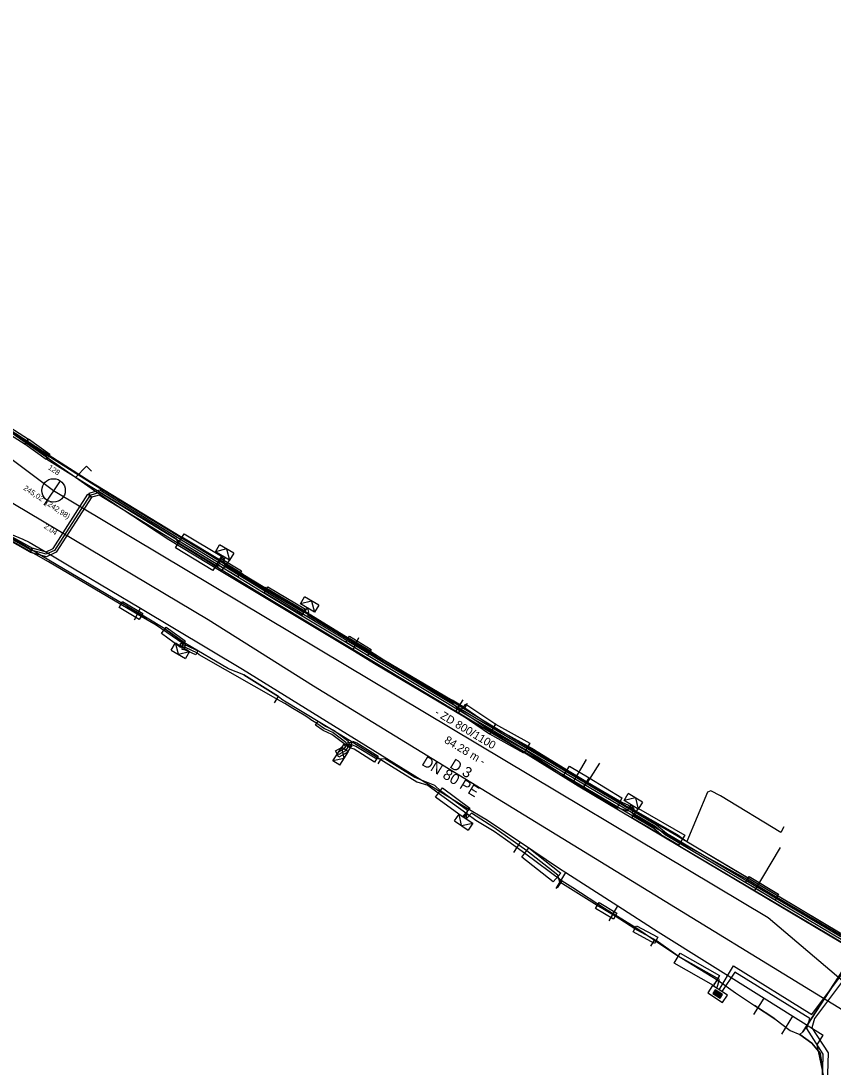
# Model space of a CAD drawing. Extents: x -600636 to -600148, y -1203980 to -1203569.
# Drawn here: x -600313.9 to -600244.6, y -1203728.9 to -1203639.7 of the extents above; entities that cross this region are included whole.
import ezdxf

# ---------------------------------------------------------------- set-up
doc = ezdxf.new("R2010")
doc.units = 0
for name, color, linetype in [('Cetin zam průběh', 7, 'Continuous'), ('EON objekty', 7, 'Continuous'), ('EON podzemní NN', 7, 'Continuous'), ('EON podzemní VN', 7, 'Continuous'), ('GasNet NTL', 7, 'Continuous'), ('Implicitní', 7, 'Continuous'), ('VaK Břeclav_kanalizace', 7, 'Continuous'), ('VaK Břeclav_kanalizace_popis', 7, 'Continuous'), ('Vak Břeclav_vodovod', 7, 'Continuous'), ('Vak Břeclav_vodovod_popis', 7, 'Continuous'), ('Vrstva 9', 7, 'Continuous')]:
    doc.layers.add(name, color=color, linetype=linetype)

# ---------------------------------------------------------------- blocks, each defined once
blk = doc.blocks.new('NN630')
at = {"layer": 'Vrstva 9'}
for points in [[(-0.003, -0.7), (-0.703, 0)], [(-0.703, -0.7), (-0.703, 0), (0.697, 0), (0.697, -0.7)], [(-0.703, -0.7), (0.697, -0.7)], [(-0.003, -0.7), (0.697, 0)]]:
    blk.add_lwpolyline(points, dxfattribs=at)
blk = doc.blocks.new('NN620')
at = {"layer": 'EON objekty'}
for points in [[(0.752, 0.004), (-0.748, 0.004)], [(-0.748, 0.004), (-0.748, -0.746)], [(0.752, -0.746), (0.752, 0.004)], [(-0.748, -0.746), (0.752, -0.746)], [(0.368, -0.18), (-0.376, -0.18)], [(-0.376, -0.18), (-0.376, -0.558)], [(-0.376, -0.558), (0.368, -0.558)], [(0.321, -0.227), (-0.329, -0.227)], [(-0.329, -0.227), (-0.329, -0.51)], [(-0.329, -0.51), (0.321, -0.51)], [(0.274, -0.274), (-0.281, -0.274)], [(-0.281, -0.274), (-0.281, -0.463)], [(-0.281, -0.463), (0.274, -0.463)], [(0.227, -0.321), (-0.234, -0.321)], [(-0.234, -0.321), (-0.234, -0.416)], [(-0.234, -0.416), (0.227, -0.416)], [(-0.193, -0.369), (0.185, -0.369)], [(0.227, -0.416), (0.227, -0.321)], [(0.274, -0.463), (0.274, -0.274)], [(0.321, -0.51), (0.321, -0.227)], [(0.368, -0.558), (0.368, -0.18)]]:
    blk.add_lwpolyline(points, dxfattribs=at)
blk = doc.blocks.new('MoSymbol 2')
at = {"layer": 'Implicitní'}
blk.add_line((0, 0.0005), (0, -0.00075), dxfattribs=at)
blk.add_circle((0, 0), 0.0005, dxfattribs=at)

msp = doc.modelspace()

# ---------------------------------------------------------------- linework, layer by layer
at = {"layer": 'Cetin zam průběh'}
for points in [[(-600324.05, -1203667.87), (-600323.52, -1203668.21), (-600317.28, -1203673.02), (-600311.48, -1203676.78)], [(-600329.02, -1203689.27), (-600327.65, -1203686.16), (-600327.07, -1203683.69), (-600326.94, -1203681.95), (-600327.13, -1203680.22), (-600326.9, -1203679.6), (-600320.9, -1203672.11), (-600319.87, -1203671.25), (-600312.14, -1203676.45), (-600307.68, -1203679.27), (-600299.7, -1203684.11), (-600292.77, -1203688.32), (-600284.45, -1203693.32), (-600273.46, -1203699.98), (-600262.73, -1203706.4), (-600257.97, -1203709.2), (-600243.31, -1203717.93), (-600240.56, -1203720.13), (-600238.73, -1203718.32)], [(-600311.48, -1203676.78), (-600308.02, -1203678.98), (-600300.16, -1203683.75), (-600296.66, -1203685.85)], [(-600291.91, -1203697.34), (-600294.89, -1203695.51), (-600296.18, -1203694.98), (-600299.85, -1203692.83), (-600301.61, -1203691.58), (-600303.13, -1203690.66), (-600304.86, -1203689.65), (-600306.01, -1203688.96), (-600312.14, -1203685.36), (-600314.73, -1203683.76), (-600316.09, -1203686.08)], [(-600296.66, -1203685.85), (-600300.16, -1203683.75)], [(-600296.48, -1203685.48), (-600296.66, -1203685.85)], [(-600296.66, -1203685.85), (-600294.96, -1203686.9), (-600293.09, -1203688.05), (-600289.68, -1203690.08)], [(-600294.96, -1203686.9), (-600296.66, -1203685.85)], [(-600289.68, -1203690.08), (-600293.09, -1203688.05)], [(-600304.86, -1203689.65), (-600303.13, -1203690.66)], [(-600289.49, -1203689.79), (-600289.68, -1203690.08)], [(-600289.68, -1203690.08), (-600285.85, -1203692.43), (-600284.14, -1203693.46), (-600282.94, -1203694.21), (-600277.12, -1203697.66), (-600276.04, -1203698.31)], [(-600301.61, -1203691.58), (-600299.85, -1203692.83)], [(-600284.14, -1203693.46), (-600285.85, -1203692.43)], [(-600294.89, -1203695.51), (-600291.91, -1203697.34), (-600291.56, -1203697.63)], [(-600292.25, -1203697.88), (-600291.91, -1203697.34)], [(-600291.91, -1203697.34), (-600291.56, -1203697.63), (-600286.6, -1203700.62), (-600283.2, -1203702.71)], [(-600276.04, -1203698.31), (-600277.12, -1203697.66)], [(-600275.84, -1203697.95), (-600276.04, -1203698.31)], [(-600276.04, -1203698.31), (-600273.76, -1203699.87), (-600270.09, -1203701.9), (-600267.29, -1203703.62), (-600265.58, -1203704.65)], [(-600270.09, -1203701.9), (-600273.76, -1203699.87)], [(-600286.6, -1203700.62), (-600283.2, -1203702.71)], [(-600283.43, -1203703.09), (-600283.2, -1203702.71)], [(-600283.2, -1203702.71), (-600282.28, -1203703.27)], [(-600283.2, -1203702.71), (-600282.28, -1203703.27), (-600280.12, -1203704.63), (-600279.19, -1203704.89), (-600278.3, -1203705.56), (-600275.87, -1203707.32)], [(-600264.56, -1203703.03), (-600265.29, -1203704.19), (-600265.58, -1203704.65)], [(-600267.29, -1203703.62), (-600265.58, -1203704.65)], [(-600265.58, -1203704.65), (-600264.28, -1203705.42), (-600262.66, -1203706.35), (-600262.08, -1203706.6), (-600261.48, -1203707.09), (-600257.92, -1203709.1), (-600257.1, -1203709.7)], [(-600278.3, -1203705.56), (-600275.87, -1203707.32), (-600275.09, -1203707.89)], [(-600264.28, -1203705.42), (-600262.66, -1203706.35)], [(-600248.84, -1203708.46), (-600249.1, -1203708.93), (-600254.24, -1203705.82), (-600255.07, -1203705.38), (-600255.33, -1203705.51), (-600257.1, -1203709.7)], [(-600276.07, -1203707.62), (-600275.87, -1203707.32)], [(-600275.87, -1203707.32), (-600275.09, -1203707.89), (-600273.54, -1203708.82), (-600272.57, -1203709.5), (-600270.94, -1203710.66), (-600267.74, -1203713.06)], [(-600261.48, -1203707.09), (-600257.92, -1203709.1)], [(-600272.57, -1203709.5), (-600270.94, -1203710.66)], [(-600257.1, -1203709.7), (-600251.89, -1203712.81), (-600249.32, -1203714.35), (-600243.88, -1203717.57)], [(-600270.94, -1203710.66), (-600267.74, -1203713.06)], [(-600251.89, -1203712.81), (-600249.32, -1203714.35)], [(-600268.14, -1203713.65), (-600267.74, -1203713.06)], [(-600267.74, -1203713.06), (-600266.84, -1203713.62)], [(-600267.74, -1203713.06), (-600266.84, -1203713.62), (-600264.12, -1203715.38), (-600262.42, -1203716.44), (-600261.46, -1203717.05), (-600259.85, -1203718.12)], [(-600264.12, -1203715.38), (-600262.42, -1203716.44)], [(-600261.46, -1203717.05), (-600259.85, -1203718.12)], [(-600260.18, -1203718.63), (-600259.85, -1203718.12)], [(-600259.85, -1203718.12), (-600258.03, -1203719.35), (-600254.47, -1203721.54)], [(-600242.68, -1203718.95), (-600247.22, -1203725.93), (-600247.46, -1203726.17)], [(-600247.22, -1203725.93), (-600242.68, -1203718.95)], [(-600258.03, -1203719.35), (-600254.47, -1203721.54)], [(-600254.79, -1203721.87), (-600254.47, -1203721.54)], [(-600254.47, -1203721.54), (-600252.97, -1203722.6), (-600251.33, -1203723.7), (-600249.6, -1203724.82), (-600248.3, -1203725.81), (-600247.46, -1203726.17)], [(-600249.6, -1203724.82), (-600251.33, -1203723.7)], [(-600247.46, -1203726.17), (-600246.45, -1203726.91), (-600245.74, -1203727.75), (-600245.58, -1203728.9), (-600245.6, -1203730.45)], [(-600245.58, -1203728.9), (-600245.74, -1203727.75), (-600246.45, -1203726.91), (-600247.46, -1203726.17)]]:
    msp.add_lwpolyline(points, dxfattribs=at)
at = {"layer": 'EON podzemní NN'}
for points in [[(-600317.616, -1203673.271), (-600317.317, -1203672.8), (-600313.236, -1203675.395), (-600313.532, -1203675.861)], [(-600313.563, -1203675.843), (-600313.234, -1203675.382), (-600311.41, -1203676.688), (-600311.738, -1203677.146)], [(-600300.695, -1203684.673), (-600299.967, -1203683.464), (-600296.78, -1203685.382), (-600297.508, -1203686.591)], [(-600297.174, -1203686.078), (-600296.864, -1203685.563), (-600295.084, -1203686.636), (-600295.393, -1203687.149)], [(-600292.836, -1203687.982), (-600289.63, -1203689.898), (-600289.938, -1203690.414), (-600293.144, -1203688.498)], [(-600305.514, -1203689.769), (-600305.208, -1203689.246), (-600303.482, -1203690.257), (-600303.788, -1203690.78)], [(-600301.888, -1203691.978), (-600301.486, -1203691.427), (-600299.873, -1203692.605), (-600300.277, -1203693.157)], [(-600285.865, -1203692.21), (-600284.029, -1203693.336), (-600284.343, -1203693.848), (-600286.179, -1203692.722)], [(-600300.3, -1203693.134), (-600300.29, -1203692.814), (-600299.89, -1203692.826), (-600299.9, -1203693.146)], [(-600300.067, -1203692.943), (-600299.74, -1203692.997), (-600298.795, -1203693.439), (-600298.965, -1203693.801), (-600299.86, -1203693.383), (-600300.133, -1203693.337)], [(-600273.409, -1203699.698), (-600273.933, -1203700.55), (-600276.27, -1203698.969), (-600276.591, -1203698.775), (-600275.941, -1203698.007), (-600273.398, -1203699.704)], [(-600288.527, -1203699.455), (-600287.9, -1203699.886), (-600287.165, -1203700.238), (-600286.036, -1203701.096), (-600285.865, -1203701.403), (-600286.215, -1203701.597), (-600286.344, -1203701.364), (-600287.375, -1203700.582), (-600288.1, -1203700.234), (-600288.753, -1203699.785)], [(-600273.409, -1203699.698), (-600270.5, -1203701.322), (-600270.492, -1203701.328), (-600271.009, -1203702.183), (-600273.911, -1203700.563)], [(-600285.786, -1203701.659), (-600286.077, -1203702.125), (-600286.766, -1203702.503), (-600287.054, -1203701.977), (-600286.503, -1203701.675), (-600286.294, -1203701.341)], [(-600285.683, -1203701.637), (-600286.003, -1203701.697), (-600286.077, -1203701.303), (-600285.757, -1203701.243)], [(-600285.615, -1203701.161), (-600285.232, -1203701.295), (-600283.423, -1203702.429), (-600283.74, -1203702.948), (-600285.482, -1203701.847), (-600285.828, -1203701.722)], [(-600267.119, -1203703.294), (-600265.443, -1203704.286), (-600265.958, -1203705.144), (-600267.639, -1203704.148)], [(-600265.959, -1203705.137), (-600265.444, -1203704.28), (-600262.635, -1203705.987), (-600263.086, -1203706.883), (-600264.674, -1203705.923)], [(-600278.547, -1203705.932), (-600277.934, -1203705.142), (-600275.594, -1203706.853), (-600276.228, -1203707.602)], [(-600257.273, -1203709.163), (-600257.809, -1203710.007), (-600261.809, -1203707.68), (-600261.218, -1203706.887)], [(-600271.174, -1203711.054), (-600270.575, -1203710.254), (-600267.847, -1203712.394), (-600268.505, -1203713.146)], [(-600251.791, -1203712.692), (-600249.277, -1203714.182), (-600249.583, -1203714.698), (-600252.097, -1203713.208)], [(-600263.068, -1203715.801), (-600263.372, -1203716.319), (-600264.892, -1203715.429), (-600264.588, -1203714.911)], [(-600259.581, -1203717.872), (-600259.869, -1203718.398), (-600261.674, -1203717.413), (-600261.386, -1203716.887)], [(-600257.683, -1203719.22), (-600254.324, -1203721.121), (-600254.82, -1203721.993), (-600258.197, -1203720.077)]]:
    msp.add_lwpolyline(points, close=True, dxfattribs=at)
for points in [[(-600317.48, -1203673.05), (-600313.39, -1203675.63), (-600311.732, -1203676.823), (-600311.676, -1203677.111), (-600308.254, -1203679.231), (-600302.831, -1203682.517), (-600300.689, -1203683.846), (-600300.476, -1203684.223), (-600297.092, -1203686.259), (-600296.7, -1203685.37), (-600296.506, -1203686.14), (-600292.99, -1203688.24), (-600289.784, -1203690.156), (-600289.701, -1203689.934), (-600289.457, -1203689.808), (-600289.351, -1203690.14), (-600289.436, -1203690.367), (-600286.022, -1203692.466), (-600284.186, -1203693.592), (-600282.9, -1203694.38), (-600277.222, -1203697.801), (-600276.338, -1203698.576), (-600276.108, -1203698.717), (-600273.765, -1203700.301), (-600270.863, -1203701.921), (-600267.571, -1203704.079), (-600264.606, -1203705.854), (-600263.018, -1203706.814), (-600262.162, -1203707.101), (-600261.863, -1203706.583), (-600261.619, -1203706.961), (-600261.8, -1203707.274), (-600261.667, -1203707.418), (-600257.658, -1203709.748), (-600257.335, -1203709.974), (-600251.944, -1203712.95), (-600249.43, -1203714.44), (-600243.42, -1203718)], [(-600300.1, -1203693.14), (-600300.09, -1203692.82), (-600302.356, -1203691.251), (-600303.624, -1203690.511), (-600305.35, -1203689.5), (-600311.54, -1203685.86), (-600314.7, -1203684.06), (-600315.49, -1203685.17), (-600316.007, -1203686.155), (-600317.63, -1203688.11), (-600321.5, -1203693.84), (-600323.385, -1203696.438)], [(-600298.69, -1203693.78), (-600298.88, -1203693.62), (-600299.8, -1203693.19), (-600300.1, -1203693.14)], [(-600289.24, -1203699.24), (-600289.722, -1203698.94), (-600290.7, -1203698.36), (-600291.386, -1203697.949), (-600291.75, -1203697.75), (-600298.69, -1203693.78)], [(-600289.24, -1203699.24), (-600288.64, -1203699.62), (-600288, -1203700.06), (-600287.27, -1203700.41), (-600286.19, -1203701.23), (-600286.095, -1203701.401), (-600286.361, -1203701.825), (-600286.871, -1203702.104), (-600286.91, -1203702.24)], [(-600254.543, -1203722.224), (-600254.324, -1203721.474), (-600257.831, -1203719.481), (-600259.725, -1203718.135), (-600261.53, -1203717.15), (-600263.22, -1203716.06), (-600264.74, -1203715.17), (-600267.926, -1203713.16), (-600268.106, -1203712.572), (-600270.76, -1203710.49), (-600273.557, -1203708.498), (-600275.458, -1203707.289), (-600275.93, -1203707.76), (-600275.797, -1203707.075), (-600278.111, -1203705.384), (-600278.579, -1203704.927), (-600280.31, -1203704.251), (-600282.869, -1203702.662), (-600283.55, -1203702.7), (-600285.319, -1203701.595), (-600285.72, -1203701.44), (-600285.907, -1203701.475), (-600286.219, -1203701.975), (-600286.774, -1203702.28), (-600286.91, -1203702.24)], [(-600241.115, -1203718.296), (-600241.956, -1203719.116), (-600246.209, -1203724.801), (-600246.442, -1203725.59), (-600245.068, -1203727.725), (-600245.152, -1203730.414), (-600245.18, -1203733.274), (-600246.203, -1203734.474), (-600259.048, -1203754.786), (-600265.34, -1203759.062), (-600294.932, -1203798.94), (-600294.8, -1203799.42), (-600294.6, -1203799.71), (-600294.639, -1203800.117), (-600301.927, -1203809.794), (-600302.189, -1203809.81)], [(-600254.356, -1203722.348), (-600253.134, -1203720.313), (-600246.441, -1203724.445), (-600242.224, -1203718.806), (-600241.428, -1203718.369)], [(-600281.885, -1203780.687), (-600273.294, -1203769.109), (-600273.288, -1203768.864), (-600273.055, -1203768.788), (-600270.904, -1203765.889), (-600270.944, -1203765.611), (-600270.666, -1203765.567), (-600265.625, -1203758.774), (-600259.342, -1203754.503), (-600251.131, -1203741.518), (-600251.247, -1203741.205), (-600250.916, -1203741.179), (-600246.523, -1203734.232), (-600245.578, -1203733.124), (-600245.552, -1203730.406), (-600245.472, -1203727.837), (-600246.878, -1203725.652), (-600246.627, -1203724.801), (-600253.016, -1203720.855), (-600254.117, -1203722.507)]]:
    msp.add_lwpolyline(points, dxfattribs=at)
at = {"layer": 'EON podzemní VN'}
msp.add_lwpolyline([(-600234.267, -1203709.224), (-600239.387, -1203717.969), (-600239.987, -1203718.569), (-600241.037, -1203718.959), (-600243.657, -1203718.239), (-600258.967, -1203709.149), (-600259.807, -1203708.439), (-600275.307, -1203699.269), (-600292.687, -1203688.819), (-600307.187, -1203679.949), (-600308.007, -1203680.199), (-600311.007, -1203684.889), (-600311.727, -1203685.219), (-600313.007, -1203684.869), (-600314.967, -1203683.759)], dxfattribs=at)
for points in [[(-600243.759, -1203718.411), (-600259.083, -1203709.312), (-600259.923, -1203708.602), (-600275.409, -1203699.441), (-600292.79, -1203688.99), (-600307.214, -1203680.166), (-600307.948, -1203680.39), (-600308.065, -1203680.008), (-600307.159, -1203679.731), (-600292.583, -1203688.648), (-600275.204, -1203699.097), (-600259.69, -1203708.275), (-600258.85, -1203708.985), (-600243.555, -1203718.067)], [(-600308.175, -1203680.091), (-600307.838, -1203680.307), (-600310.87, -1203685.046), (-600311.709, -1203685.431), (-600313.059, -1203685.062), (-600312.954, -1203684.676), (-600311.744, -1203685.007), (-600311.143, -1203684.732)], [(-600313.105, -1203685.043), (-600315.002, -1203683.969), (-600315.971, -1203684.146), (-600316.043, -1203683.752), (-600314.931, -1203683.549), (-600312.908, -1203684.695)]]:
    msp.add_lwpolyline(points, close=True, dxfattribs=at)
at = {"layer": 'GasNet NTL'}
for points in [[(-600240.2, -1203720.25), (-600242.49, -1203719.1), (-600242.92, -1203718.93), (-600251.35, -1203713.94), (-600251.9, -1203713.61), (-600266.36, -1203704.99), (-600266.82, -1203704.7), (-600272.19, -1203701.39), (-600276.83, -1203698.64), (-600283.58, -1203694.63), (-600285.57, -1203693.43), (-600296.81, -1203686.68), (-600301.28, -1203684), (-600307.41, -1203679.95), (-600309.24, -1203678.67), (-600322.08, -1203669.74)], [(-600328.46, -1203677.78), (-600313.71, -1203683.92), (-600313.19, -1203684.18), (-600311.2, -1203685.34), (-600309.19, -1203686.55), (-600308.85, -1203686.75), (-600303.69, -1203689.82), (-600294.98, -1203695.01), (-600276.12, -1203706.69), (-600274.1, -1203707.89), (-600273.98, -1203707.97), (-600271.3, -1203709.76), (-600267.96, -1203712), (-600267.43, -1203712.34), (-600262.98, -1203715.2), (-600259.56, -1203717.4), (-600250.52, -1203723.06), (-600248.07, -1203724.6), (-600245.48, -1203726.22)], [(-600309.24, -1203678.67), (-600308.3, -1203677.7), (-600307.87, -1203678.12)], [(-600296.81, -1203686.68), (-600296.02, -1203685.64)], [(-600304.2, -1203690.81), (-600303.69, -1203689.82)], [(-600285.57, -1203693.43), (-600285.06, -1203692.32)], [(-600276.83, -1203698.64), (-600276.17, -1203697.62)], [(-600266.82, -1203704.7), (-600265.67, -1203702.71)], [(-600271.85, -1203710.64), (-600271.3, -1203709.76)], [(-600251.35, -1203713.94), (-600249.11, -1203710.215)], [(-600268.25, -1203713.7), (-600267.43, -1203712.34)], [(-600263.72, -1203716.46), (-600262.98, -1203715.2)], [(-600251.4, -1203724.46), (-600250.52, -1203723.06)], [(-600249.02, -1203726.12), (-600248.07, -1203724.6)], [(-600295.95, -1203801.21), (-600295.65, -1203800.81), (-600287.36, -1203789.82), (-600286.53, -1203788.7), (-600278.7, -1203778.11), (-600278.55, -1203777.91), (-600275.98, -1203774.4), (-600270.38, -1203766.79), (-600268.42, -1203764.21), (-600266.21, -1203761.3), (-600264.99, -1203760.1), (-600261.02, -1203756.81), (-600258.4, -1203754.89), (-600252.86, -1203745.77), (-600247.26, -1203737.18), (-600244.78, -1203732.86), (-600245.17, -1203730.96), (-600245.99, -1203727.04), (-600245.48, -1203726.22)]]:
    msp.add_lwpolyline(points, dxfattribs=at)
at = {"layer": 'VaK Břeclav_kanalizace'}
msp.add_line((-600367.912, -1203637.359), (-600311.102, -1203679.776), dxfattribs=at)
msp.add_lwpolyline([(-600311.102, -1203679.776), (-600279.472, -1203698.674), (-600250.164, -1203716.186), (-600240.031, -1203724.796)], dxfattribs=at)
at = {"layer": 'Vak Břeclav_vodovod'}
msp.add_lwpolyline([(-600236.89, -1203728.365), (-600242.377, -1203724.953), (-600264, -1203711.729), (-600288.949, -1203696.473), (-600297.916, -1203690.812), (-600315.791, -1203680.191)], dxfattribs=at)

# ---------------------------------------------------------------- block references
at = {"layer": 'EON podzemní NN'}
for name, p, rotation in [('NN630', (-600296.7, -1203685.37), 149.51477220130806), ('NN630', (-600289.457, -1203689.808), 149.637588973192), ('NN630', (-600300.1, -1203693.14), -30.63541752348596), ('NN630', (-600286.91, -1203702.24), 57.26480238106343), ('NN630', (-600261.863, -1203706.583), 148.73556951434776), ('NN630', (-600275.93, -1203707.76), -33.82341392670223), ('NN620', (-600254.285, -1203722.397), -32.78073615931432)]:
    msp.add_blockref(name, p, dxfattribs=dict(at, rotation=rotation))
at = {"layer": 'VaK Břeclav_kanalizace', "xscale": 1999.7500312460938, "yscale": 1999.7500312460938, "rotation": -33.80236952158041}
msp.add_blockref('MoSymbol 2', (-600311.102, -1203679.776), dxfattribs=at)

# ---------------------------------------------------------------- texts
at = {"layer": 'VaK Břeclav_kanalizace_popis'}
for s, height, rotation, p in [('128', 0.4549, 326.19763, (-600311.615, -1203677.933)), ('245,02  (242,98)', 0.45494, 326.19763, (-600313.713, -1203679.675)), ('2.04', 0.4549, 326.19763, (-600311.967, -1203682.944)), ('- ZD 800/1100', 0.68241, 329.142, (-600278.664, -1203698.875)), ('84.28 m -', 0.6824, 329.142, (-600277.842, -1203701.243))]:
    msp.add_text(s, height=height, rotation=rotation, dxfattribs=at).set_placement(p)
at = {"layer": 'Vak Břeclav_vodovod_popis'}
for s, p in [('DN 80 PE', (-600279.787, -1203703.142)), ('D 3', (-600277.39, -1203703.365))]:
    msp.add_text(s, height=0.9099, rotation=328.55474, dxfattribs=at).set_placement(p)

doc.saveas('drawing.dxf')
